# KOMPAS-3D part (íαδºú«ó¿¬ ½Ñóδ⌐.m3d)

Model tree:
1. Эскиз:1
2. Операция выдавливания:1
     Расстояние 1 = 39; Расстояние 2 = 1
3. Эскиз:2
4. Вырезать элемент выдавливания:1
     Расстояние 1 = 45
5. Эскиз:3
6. Операция выдавливания:2
     Расстояние 1 = 6.3; Расстояние 2 = 1
7. Скругление:6
     Радиус = 1
8. Эскиз:10
9. Вырезать элемент выдавливания:8
     Расстояние 1 = 5
10. Эскиз:13
11. Операция выдавливания:4
     Расстояние 1 = 0.5
12. Скругление:13
     Радиус = 0.5
13. Эскиз:15
14. Вырезать элемент выдавливания:11
     Расстояние 1 = 45
15. Фаска:3
     Угол = 45; Длина 1 = 4; Длина 2 = 4
16. Сплайновая форма:2
17. Скругление:15
     Радиус = 2
18. Скругление:16
     Радиус = 2
19. Скругление:18
     Радиус = 2
20. Скругление:19
     Радиус = 2
21. Эскиз:18
22. Вырезать элемент выдавливания:14
     Расстояние 1 = 30; Угол 1 = 11
23. Эскиз:19
24. Вырезать элемент выдавливания:15
     Расстояние 1 = 12; Угол 1 = 22
25. Эскиз:20
26. Вырезать элемент выдавливания:16
     Расстояние 1 = 4; Угол 1 = 22
27. Эскиз:21
28. Операция выдавливания:5
     Расстояние 1 = 50
29. Эскиз:23
30. Вырезать элемент выдавливания:17
     Расстояние 2 = 6; Расстояние 1 = 4
31. Скругление:20
     Радиус = 2

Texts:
  Сплав АЛ8  ГОСТ 1583-93
  stalker61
